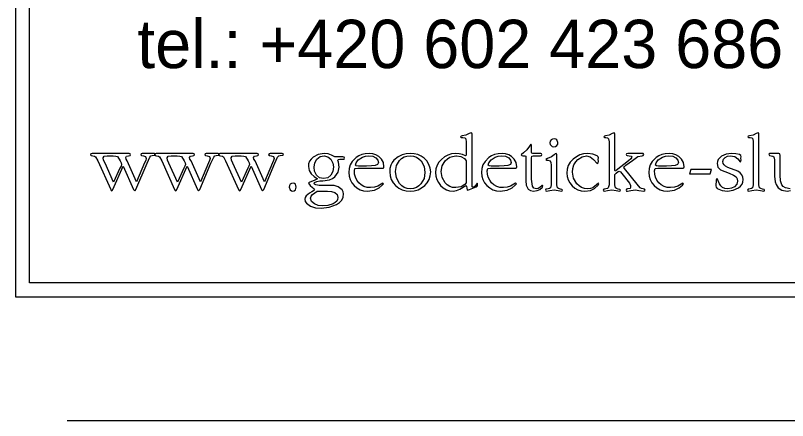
# Model space of a CAD drawing. Extents: x -866693 to -866303, y -1041966 to -1040244.
# Drawn here: x -866432.68 to -866414.49, y -1041642.86 to -1041633.31 of the extents above; entities that cross this region are included whole.
import ezdxf

# ---------------------------------------------------------------- set-up
doc = ezdxf.new("R2010")
doc.units = 0
doc.layers.add('Tabulka', color=7, linetype='Continuous')

msp = doc.modelspace()

# ---------------------------------------------------------------- linework, layer by layer
at = {"layer": 'Tabulka'}
for p, q in [((-866432.683, -1041626.437), (-866432.683, -1041639.941)), ((-866432.353, -1041639.611), (-866432.353, -1041626.768)), ((-866406.437, -1041639.611), (-866432.353, -1041639.611)), ((-866432.683, -1041639.941), (-866404.89, -1041639.941)), ((-866431.466, -1041642.862), (-866338.717, -1041642.862))]:
    msp.add_line(p, q, dxfattribs=at)
for points in [[(-866421.798, -1041637.288), (-866421.798, -1041637.269), (-866421.808, -1041637.262), (-866421.854, -1041637.336), (-866421.897, -1041637.37), (-866421.922, -1041637.351), (-866421.926, -1041637.299), (-866421.926, -1041637.269), (-866421.926, -1041636.107), (-866421.931, -1041636.084), (-866421.945, -1041636.075), (-866421.991, -1041636.097), (-866422.07, -1041636.131), (-866422.156, -1041636.15), (-866422.185, -1041636.159), (-866422.195, -1041636.173), (-866422.175, -1041636.191), (-866422.142, -1041636.191), (-866422.1, -1041636.198), (-866422.076, -1041636.216), (-866422.061, -1041636.294), (-866422.061, -1041636.325), (-866422.061, -1041636.354), (-866422.061, -1041636.545), (-866422.061, -1041636.573), (-866422.065, -1041636.606), (-866422.078, -1041636.618), (-866422.151, -1041636.592), (-866422.226, -1041636.572), (-866422.32, -1041636.565), (-866422.41, -1041636.574), (-866422.497, -1041636.602), (-866422.578, -1041636.646), (-866422.649, -1041636.703), (-866422.708, -1041636.769), (-866422.75, -1041636.843), (-866422.776, -1041636.924), (-866422.785, -1041637.01), (-866422.778, -1041637.097), (-866422.756, -1041637.177), (-866422.719, -1041637.251), (-866422.666, -1041637.32), (-866422.603, -1041637.377), (-866422.532, -1041637.418), (-866422.454, -1041637.442), (-866422.368, -1041637.45), (-866422.294, -1041637.44), (-866422.216, -1041637.409), (-866422.07, -1041637.316), (-866422.054, -1041637.337), (-866422.051, -1041637.379), (-866422.045, -1041637.419), (-866422.03, -1041637.433), (-866421.989, -1041637.414), (-866421.833, -1041637.35), (-866421.805, -1041637.337), (-866421.8, -1041637.314)], [(-866417.851, -1041637.43), (-866417.862, -1041637.405), (-866417.892, -1041637.397), (-866417.934, -1041637.392), (-866417.962, -1041637.376), (-866418.033, -1041637.287), (-866418.337, -1041636.915), (-866418.351, -1041636.891), (-866418.337, -1041636.868), (-866418.301, -1041636.839), (-866418.15, -1041636.726), (-866418.021, -1041636.636), (-866417.921, -1041636.619), (-866417.895, -1041636.615), (-866417.882, -1041636.587), (-866417.893, -1041636.566), (-866417.914, -1041636.565), (-866418.254, -1041636.565), (-866418.287, -1041636.57), (-866418.298, -1041636.586), (-866418.291, -1041636.606), (-866418.272, -1041636.615), (-866418.224, -1041636.619), (-866418.18, -1041636.625), (-866418.162, -1041636.65), (-866418.187, -1041636.692), (-866418.243, -1041636.741), (-866418.532, -1041636.968), (-866418.542, -1041636.976), (-866418.554, -1041636.982), (-866418.565, -1041636.967), (-866418.565, -1041636.941), (-866418.565, -1041636.106), (-866418.569, -1041636.084), (-866418.582, -1041636.075), (-866418.626, -1041636.097), (-866418.7, -1041636.131), (-866418.781, -1041636.15), (-866418.809, -1041636.159), (-866418.818, -1041636.173), (-866418.8, -1041636.191), (-866418.772, -1041636.191), (-866418.735, -1041636.198), (-866418.713, -1041636.216), (-866418.7, -1041636.291), (-866418.7, -1041636.321), (-866418.7, -1041636.35), (-866418.7, -1041637.242), (-866418.7, -1041637.301), (-866418.716, -1041637.373), (-866418.739, -1041637.393), (-866418.772, -1041637.401), (-866418.823, -1041637.409), (-866418.834, -1041637.431), (-866418.827, -1041637.446), (-866418.807, -1041637.45), (-866418.733, -1041637.437), (-866418.63, -1041637.423), (-866418.531, -1041637.44), (-866418.454, -1041637.45), (-866418.437, -1041637.445), (-866418.431, -1041637.428), (-866418.444, -1041637.413), (-866418.482, -1041637.403), (-866418.524, -1041637.393), (-866418.549, -1041637.372), (-866418.565, -1041637.3), (-866418.565, -1041637.241), (-866418.565, -1041637.128), (-866418.559, -1041637.056), (-866418.528, -1041637.025), (-866418.487, -1041636.992), (-866418.459, -1041636.98), (-866418.432, -1041636.995), (-866418.401, -1041637.034), (-866418.219, -1041637.267), (-866418.197, -1041637.319), (-866418.19, -1041637.356), (-866418.205, -1041637.388), (-866418.264, -1041637.397), (-866418.287, -1041637.406), (-866418.298, -1041637.432), (-866418.285, -1041637.45), (-866418.266, -1041637.45), (-866418.184, -1041637.437), (-866418.079, -1041637.423), (-866417.994, -1041637.437), (-866417.883, -1041637.45), (-866417.859, -1041637.445)], [(-866415.033, -1041637.429), (-866415.046, -1041637.413), (-866415.083, -1041637.403), (-866415.125, -1041637.393), (-866415.151, -1041637.373), (-866415.167, -1041637.302), (-866415.167, -1041637.243), (-866415.167, -1041636.107), (-866415.171, -1041636.084), (-866415.184, -1041636.075), (-866415.23, -1041636.097), (-866415.306, -1041636.131), (-866415.39, -1041636.15), (-866415.419, -1041636.159), (-866415.428, -1041636.173), (-866415.409, -1041636.191), (-866415.378, -1041636.191), (-866415.338, -1041636.198), (-866415.315, -1041636.216), (-866415.301, -1041636.291), (-866415.301, -1041636.321), (-866415.301, -1041636.35), (-866415.301, -1041637.242), (-866415.301, -1041637.301), (-866415.317, -1041637.373), (-866415.34, -1041637.393), (-866415.373, -1041637.401), (-866415.424, -1041637.409), (-866415.435, -1041637.431), (-866415.429, -1041637.446), (-866415.409, -1041637.45), (-866415.335, -1041637.437), (-866415.231, -1041637.423), (-866415.132, -1041637.44), (-866415.055, -1041637.45), (-866415.039, -1041637.445)], [(-866420.259, -1041637.329), (-866420.264, -1041637.322), (-866420.272, -1041637.316), (-866420.332, -1041637.367), (-866420.37, -1041637.39), (-866420.41, -1041637.397), (-866420.471, -1041637.381), (-866420.504, -1041637.332), (-866420.523, -1041637.168), (-866420.523, -1041636.672), (-866420.515, -1041636.629), (-866420.485, -1041636.619), (-866420.453, -1041636.619), (-866420.345, -1041636.619), (-866420.313, -1041636.619), (-866420.292, -1041636.612), (-866420.286, -1041636.589), (-866420.29, -1041636.572), (-866420.303, -1041636.565), (-866420.493, -1041636.565), (-866420.519, -1041636.56), (-866420.523, -1041636.539), (-866420.523, -1041636.372), (-866420.539, -1041636.344), (-866420.569, -1041636.389), (-866420.633, -1041636.478), (-866420.714, -1041636.55), (-866420.76, -1041636.585), (-866420.766, -1041636.6), (-866420.757, -1041636.614), (-866420.729, -1041636.619), (-866420.706, -1041636.619), (-866420.683, -1041636.619), (-866420.66, -1041636.628), (-866420.657, -1041636.654), (-866420.657, -1041637.151), (-866420.657, -1041637.212), (-866420.649, -1041637.313), (-866420.604, -1041637.404), (-866420.553, -1041637.439), (-866420.476, -1041637.45), (-866420.389, -1041637.44), (-866420.329, -1041637.41), (-866420.27, -1041637.356)], [(-866419.902, -1041636.308), (-866419.927, -1041636.245), (-866419.956, -1041636.223), (-866419.993, -1041636.216), (-866420.032, -1041636.223), (-866420.063, -1041636.245), (-866420.083, -1041636.275), (-866420.09, -1041636.313), (-866420.084, -1041636.349), (-866420.066, -1041636.379), (-866420.037, -1041636.398), (-866419.997, -1041636.404), (-866419.957, -1041636.398), (-866419.927, -1041636.376), (-866419.909, -1041636.346)], [(-866429.382, -1041636.589), (-866429.389, -1041636.572), (-866429.409, -1041636.565), (-866429.697, -1041636.565), (-866429.722, -1041636.573), (-866429.731, -1041636.598), (-866429.712, -1041636.615), (-866429.669, -1041636.619), (-866429.618, -1041636.634), (-866429.601, -1041636.68), (-866429.614, -1041636.733), (-866429.641, -1041636.787), (-866429.832, -1041637.233), (-866430.051, -1041636.741), (-866430.078, -1041636.695), (-866430.086, -1041636.662), (-866430.065, -1041636.629), (-866430.017, -1041636.619), (-866429.983, -1041636.613), (-866429.972, -1041636.595), (-866429.98, -1041636.573), (-866430.003, -1041636.565), (-866430.878, -1041636.565), (-866430.903, -1041636.573), (-866430.911, -1041636.595), (-866430.899, -1041636.613), (-866430.863, -1041636.619), (-866430.821, -1041636.626), (-866430.793, -1041636.646), (-866430.744, -1041636.734), (-866430.439, -1041637.412), (-866430.428, -1041637.434), (-866430.412, -1041637.443), (-866430.395, -1041637.433), (-866430.385, -1041637.412), (-866430.144, -1041636.86), (-866429.899, -1041637.412), (-866429.889, -1041637.429), (-866429.874, -1041637.443), (-866429.858, -1041637.433), (-866429.848, -1041637.412), (-866429.583, -1041636.79), (-866429.52, -1041636.65), (-866429.493, -1041636.622), (-866429.462, -1041636.61), (-866429.405, -1041636.602)], [(-866430.181, -1041636.821), (-866430.196, -1041636.861), (-866430.223, -1041636.907), (-866430.369, -1041637.242), (-866430.573, -1041636.789), (-866430.605, -1041636.721), (-866430.617, -1041636.668), (-866430.594, -1041636.631), (-866430.521, -1041636.619), (-866430.379, -1041636.619), (-866430.314, -1041636.624), (-866430.275, -1041636.638), (-866430.213, -1041636.737), (-866430.192, -1041636.782)], [(-866427.876, -1041636.589), (-866427.883, -1041636.572), (-866427.904, -1041636.565), (-866428.191, -1041636.565), (-866428.216, -1041636.573), (-866428.225, -1041636.598), (-866428.206, -1041636.615), (-866428.163, -1041636.619), (-866428.112, -1041636.634), (-866428.095, -1041636.68), (-866428.108, -1041636.733), (-866428.135, -1041636.787), (-866428.325, -1041637.233), (-866428.544, -1041636.741), (-866428.572, -1041636.695), (-866428.58, -1041636.662), (-866428.559, -1041636.629), (-866428.511, -1041636.619), (-866428.477, -1041636.613), (-866428.466, -1041636.595), (-866428.474, -1041636.573), (-866428.497, -1041636.565), (-866429.371, -1041636.565), (-866429.397, -1041636.573), (-866429.405, -1041636.595), (-866429.393, -1041636.613), (-866429.357, -1041636.619), (-866429.315, -1041636.626), (-866429.287, -1041636.646), (-866429.238, -1041636.734), (-866428.933, -1041637.412), (-866428.922, -1041637.434), (-866428.906, -1041637.443), (-866428.889, -1041637.433), (-866428.879, -1041637.412), (-866428.638, -1041636.86), (-866428.393, -1041637.412), (-866428.383, -1041637.429), (-866428.367, -1041637.443), (-866428.352, -1041637.433), (-866428.342, -1041637.412), (-866428.077, -1041636.79), (-866428.013, -1041636.65), (-866427.987, -1041636.622), (-866427.956, -1041636.61), (-866427.9, -1041636.602)], [(-866428.675, -1041636.821), (-866428.689, -1041636.861), (-866428.717, -1041636.907), (-866428.864, -1041637.242), (-866429.066, -1041636.789), (-866429.099, -1041636.721), (-866429.111, -1041636.668), (-866429.088, -1041636.631), (-866429.015, -1041636.619), (-866428.874, -1041636.619), (-866428.808, -1041636.624), (-866428.769, -1041636.638), (-866428.707, -1041636.737), (-866428.687, -1041636.782)], [(-866426.369, -1041636.589), (-866426.376, -1041636.572), (-866426.397, -1041636.565), (-866426.684, -1041636.565), (-866426.709, -1041636.573), (-866426.718, -1041636.598), (-866426.7, -1041636.615), (-866426.656, -1041636.619), (-866426.605, -1041636.634), (-866426.588, -1041636.68), (-866426.601, -1041636.733), (-866426.628, -1041636.787), (-866426.819, -1041637.233), (-866427.038, -1041636.741), (-866427.065, -1041636.695), (-866427.073, -1041636.662), (-866427.052, -1041636.629), (-866427.005, -1041636.619), (-866426.97, -1041636.613), (-866426.959, -1041636.595), (-866426.967, -1041636.573), (-866426.99, -1041636.565), (-866427.865, -1041636.565), (-866427.89, -1041636.573), (-866427.898, -1041636.595), (-866427.886, -1041636.613), (-866427.85, -1041636.619), (-866427.808, -1041636.626), (-866427.78, -1041636.646), (-866427.731, -1041636.734), (-866427.426, -1041637.412), (-866427.415, -1041637.434), (-866427.399, -1041637.443), (-866427.382, -1041637.433), (-866427.372, -1041637.412), (-866427.131, -1041636.86), (-866426.886, -1041637.412), (-866426.876, -1041637.429), (-866426.861, -1041637.443), (-866426.845, -1041637.433), (-866426.835, -1041637.412), (-866426.57, -1041636.79), (-866426.507, -1041636.65), (-866426.481, -1041636.622), (-866426.449, -1041636.61), (-866426.393, -1041636.602)], [(-866427.168, -1041636.821), (-866427.183, -1041636.861), (-866427.21, -1041636.907), (-866427.357, -1041637.242), (-866427.56, -1041636.789), (-866427.592, -1041636.721), (-866427.604, -1041636.668), (-866427.581, -1041636.631), (-866427.508, -1041636.619), (-866427.367, -1041636.619), (-866427.301, -1041636.624), (-866427.262, -1041636.638), (-866427.2, -1041636.737), (-866427.18, -1041636.782)], [(-866424.934, -1041636.674), (-866424.94, -1041636.654), (-866424.97, -1041636.646), (-866425.002, -1041636.646), (-866425.099, -1041636.646), (-866425.162, -1041636.642), (-866425.241, -1041636.602), (-866425.317, -1041636.574), (-866425.412, -1041636.565), (-866425.549, -1041636.587), (-866425.67, -1041636.65), (-866425.72, -1041636.696), (-866425.754, -1041636.749), (-866425.776, -1041636.808), (-866425.783, -1041636.873), (-866425.767, -1041636.964), (-866425.718, -1041637.041), (-866425.648, -1041637.105), (-866425.567, -1041637.159), (-866425.63, -1041637.196), (-866425.763, -1041637.246), (-866425.783, -1041637.265), (-866425.742, -1041637.317), (-866425.687, -1041637.367), (-866425.654, -1041637.396), (-866425.637, -1041637.423), (-866425.658, -1041637.447), (-866425.703, -1041637.472), (-866425.756, -1041637.502), (-866425.836, -1041637.563), (-866425.856, -1041637.599), (-866425.863, -1041637.643), (-866425.854, -1041637.694), (-866425.824, -1041637.738), (-866425.729, -1041637.805), (-866425.613, -1041637.842), (-866425.477, -1041637.852), (-866425.295, -1041637.832), (-866425.121, -1041637.768), (-866425.047, -1041637.721), (-866424.993, -1041637.663), (-866424.962, -1041637.595), (-866424.951, -1041637.517), (-866424.96, -1041637.465), (-866424.989, -1041637.42), (-866425.083, -1041637.35), (-866425.178, -1041637.32), (-866425.316, -1041637.316), (-866425.529, -1041637.316), (-866425.608, -1041637.305), (-866425.638, -1041637.29), (-866425.648, -1041637.269), (-866425.635, -1041637.248), (-866425.579, -1041637.228), (-866425.515, -1041637.212), (-866425.438, -1041637.209), (-866425.285, -1041637.185), (-866425.216, -1041637.154), (-866425.159, -1041637.111), (-866425.083, -1041637.005), (-866425.058, -1041636.885), (-866425.074, -1041636.767), (-866425.088, -1041636.718), (-866425.078, -1041636.704), (-866425.044, -1041636.7), (-866425.009, -1041636.7), (-866424.975, -1041636.7), (-866424.94, -1041636.696)], [(-866425.192, -1041636.882), (-866425.208, -1041636.989), (-866425.252, -1041637.077), (-866425.326, -1041637.136), (-866425.428, -1041637.156), (-866425.522, -1041637.135), (-866425.592, -1041637.073), (-866425.634, -1041636.985), (-866425.648, -1041636.884), (-866425.632, -1041636.785), (-866425.584, -1041636.698), (-866425.508, -1041636.639), (-866425.411, -1041636.619), (-866425.323, -1041636.64), (-866425.253, -1041636.702), (-866425.208, -1041636.789)], [(-866424.001, -1041636.881), (-866424.016, -1041636.78), (-866424.061, -1041636.696), (-866424.123, -1041636.633), (-866424.191, -1041636.593), (-866424.265, -1041636.572), (-866424.346, -1041636.565), (-866424.441, -1041636.572), (-866424.524, -1041636.589), (-866424.597, -1041636.62), (-866424.658, -1041636.661), (-866424.749, -1041636.753), (-866424.801, -1041636.834), (-866424.824, -1041636.917), (-866424.832, -1041637.012), (-866424.825, -1041637.1), (-866424.801, -1041637.18), (-866424.761, -1041637.255), (-866424.706, -1041637.322), (-866424.639, -1041637.378), (-866424.564, -1041637.419), (-866424.482, -1041637.442), (-866424.392, -1041637.45), (-866424.227, -1041637.428), (-866424.112, -1041637.373), (-866424.04, -1041637.314), (-866424.011, -1041637.277), (-866424.027, -1041637.262), (-866424.149, -1041637.337), (-866424.228, -1041637.362), (-866424.317, -1041637.37), (-866424.399, -1041637.363), (-866424.473, -1041637.341), (-866424.538, -1041637.305), (-866424.594, -1041637.254), (-866424.639, -1041637.193), (-866424.672, -1041637.126), (-866424.692, -1041637.052), (-866424.698, -1041636.973), (-866424.684, -1041636.921), (-866424.618, -1041636.914), (-866424.024, -1041636.914), (-866424.006, -1041636.906)], [(-866424.134, -1041636.776), (-866424.153, -1041636.823), (-866424.212, -1041636.847), (-866424.296, -1041636.858), (-866424.415, -1041636.86), (-866424.441, -1041636.86), (-866424.603, -1041636.86), (-866424.654, -1041636.858), (-866424.672, -1041636.838), (-866424.655, -1041636.785), (-866424.607, -1041636.716), (-866424.509, -1041636.649), (-866424.439, -1041636.626), (-866424.362, -1041636.619), (-866424.264, -1041636.631), (-866424.191, -1041636.669), (-866424.149, -1041636.723)], [(-866422.9, -1041637), (-866422.911, -1041636.91), (-866422.942, -1041636.821), (-866422.99, -1041636.741), (-866423.053, -1041636.675), (-866423.126, -1041636.625), (-866423.205, -1041636.591), (-866423.29, -1041636.572), (-866423.383, -1041636.565), (-866423.482, -1041636.573), (-866423.575, -1041636.596), (-866423.668, -1041636.644), (-866423.766, -1041636.723), (-866423.81, -1041636.776), (-866423.841, -1041636.84), (-866423.86, -1041636.915), (-866423.866, -1041637), (-866423.858, -1041637.094), (-866423.831, -1041637.179), (-866423.788, -1041637.255), (-866423.726, -1041637.323), (-866423.652, -1041637.379), (-866423.57, -1041637.419), (-866423.481, -1041637.442), (-866423.383, -1041637.45), (-866423.287, -1041637.442), (-866423.198, -1041637.419), (-866423.116, -1041637.378), (-866423.042, -1041637.322), (-866422.98, -1041637.254), (-866422.936, -1041637.177), (-866422.91, -1041637.093)], [(-866423.035, -1041637.013), (-866423.058, -1041637.151), (-866423.129, -1041637.277), (-866423.179, -1041637.33), (-866423.238, -1041637.367), (-866423.304, -1041637.39), (-866423.376, -1041637.397), (-866423.454, -1041637.389), (-866423.522, -1041637.365), (-866423.583, -1041637.326), (-866423.635, -1041637.269), (-866423.708, -1041637.137), (-866423.732, -1041636.992), (-866423.709, -1041636.851), (-866423.638, -1041636.73), (-866423.588, -1041636.682), (-866423.528, -1041636.647), (-866423.461, -1041636.626), (-866423.384, -1041636.619), (-866423.307, -1041636.626), (-866423.238, -1041636.649), (-866423.178, -1041636.687), (-866423.127, -1041636.74), (-866423.058, -1041636.868)], [(-866422.061, -1041637.189), (-866422.061, -1041637.22), (-866422.065, -1041637.254), (-866422.094, -1041637.298), (-866422.183, -1041637.349), (-866422.312, -1041637.37), (-866422.385, -1041637.363), (-866422.451, -1041637.341), (-866422.509, -1041637.305), (-866422.559, -1041637.255), (-866422.628, -1041637.133), (-866422.651, -1041636.992), (-866422.628, -1041636.855), (-866422.558, -1041636.739), (-866422.507, -1041636.691), (-866422.449, -1041636.655), (-866422.384, -1041636.632), (-866422.31, -1041636.619), (-866422.29, -1041636.619), (-866422.189, -1041636.635), (-866422.107, -1041636.679), (-866422.068, -1041636.741), (-866422.061, -1041636.829), (-866422.061, -1041636.852)], [(-866420.872, -1041636.881), (-866420.887, -1041636.78), (-866420.932, -1041636.696), (-866420.995, -1041636.633), (-866421.062, -1041636.593), (-866421.136, -1041636.572), (-866421.217, -1041636.565), (-866421.313, -1041636.572), (-866421.396, -1041636.589), (-866421.469, -1041636.62), (-866421.529, -1041636.661), (-866421.62, -1041636.753), (-866421.672, -1041636.834), (-866421.696, -1041636.917), (-866421.704, -1041637.012), (-866421.696, -1041637.1), (-866421.672, -1041637.18), (-866421.633, -1041637.255), (-866421.577, -1041637.322), (-866421.51, -1041637.378), (-866421.435, -1041637.419), (-866421.353, -1041637.442), (-866421.263, -1041637.45), (-866421.099, -1041637.428), (-866420.984, -1041637.373), (-866420.912, -1041637.314), (-866420.883, -1041637.277), (-866420.899, -1041637.262), (-866421.02, -1041637.337), (-866421.1, -1041637.362), (-866421.189, -1041637.37), (-866421.271, -1041637.363), (-866421.344, -1041637.341), (-866421.41, -1041637.305), (-866421.466, -1041637.254), (-866421.511, -1041637.193), (-866421.543, -1041637.126), (-866421.563, -1041637.052), (-866421.569, -1041636.973), (-866421.556, -1041636.921), (-866421.489, -1041636.914), (-866420.896, -1041636.914), (-866420.878, -1041636.906)], [(-866421.006, -1041636.776), (-866421.024, -1041636.823), (-866421.083, -1041636.847), (-866421.168, -1041636.858), (-866421.287, -1041636.86), (-866421.313, -1041636.86), (-866421.475, -1041636.86), (-866421.525, -1041636.858), (-866421.543, -1041636.838), (-866421.527, -1041636.785), (-866421.479, -1041636.716), (-866421.38, -1041636.649), (-866421.31, -1041636.626), (-866421.233, -1041636.619), (-866421.136, -1041636.631), (-866421.063, -1041636.669), (-866421.02, -1041636.723)], [(-866419.795, -1041637.429), (-866419.808, -1041637.413), (-866419.846, -1041637.404), (-866419.888, -1041637.393), (-866419.913, -1041637.373), (-866419.929, -1041637.303), (-866419.929, -1041637.245), (-866419.929, -1041636.596), (-866419.933, -1041636.573), (-866419.946, -1041636.565), (-866419.967, -1041636.573), (-866419.991, -1041636.597), (-866420.055, -1041636.642), (-866420.146, -1041636.682), (-866420.187, -1041636.71), (-866420.164, -1041636.724), (-866420.139, -1041636.724), (-866420.084, -1041636.737), (-866420.069, -1041636.779), (-866420.063, -1041636.839), (-866420.063, -1041636.867), (-866420.063, -1041637.24), (-866420.063, -1041637.3), (-866420.08, -1041637.372), (-866420.102, -1041637.392), (-866420.136, -1041637.401), (-866420.187, -1041637.409), (-866420.198, -1041637.431), (-866420.191, -1041637.446), (-866420.171, -1041637.45), (-866420.097, -1041637.437), (-866419.993, -1041637.423), (-866419.895, -1041637.44), (-866419.818, -1041637.45), (-866419.801, -1041637.445)], [(-866418.938, -1041637.279), (-866418.951, -1041637.262), (-866418.991, -1041637.304), (-866419.08, -1041637.372), (-866419.138, -1041637.39), (-866419.201, -1041637.397), (-866419.276, -1041637.39), (-866419.344, -1041637.367), (-866419.405, -1041637.33), (-866419.459, -1041637.277), (-866419.536, -1041637.149), (-866419.561, -1041637.005), (-866419.552, -1041636.919), (-866419.525, -1041636.835), (-866419.484, -1041636.762), (-866419.435, -1041636.707), (-866419.33, -1041636.641), (-866419.228, -1041636.619), (-866419.143, -1041636.642), (-866419.067, -1041636.708), (-866418.976, -1041636.798), (-866418.956, -1041636.785), (-866418.951, -1041636.743), (-866418.953, -1041636.705), (-866418.951, -1041636.67), (-866418.959, -1041636.64), (-866418.981, -1041636.616), (-866419.077, -1041636.58), (-866419.201, -1041636.565), (-866419.297, -1041636.574), (-866419.386, -1041636.599), (-866419.469, -1041636.641), (-866419.546, -1041636.7), (-866419.612, -1041636.771), (-866419.659, -1041636.849), (-866419.686, -1041636.934), (-866419.695, -1041637.025), (-866419.688, -1041637.109), (-866419.664, -1041637.187), (-866419.626, -1041637.259), (-866419.57, -1041637.324), (-866419.505, -1041637.38), (-866419.433, -1041637.419), (-866419.355, -1041637.443), (-866419.27, -1041637.45), (-866419.133, -1041637.436), (-866419.043, -1041637.393), (-866418.957, -1041637.313)], [(-866416.932, -1041636.881), (-866416.947, -1041636.78), (-866416.992, -1041636.696), (-866417.054, -1041636.633), (-866417.122, -1041636.593), (-866417.197, -1041636.572), (-866417.277, -1041636.565), (-866417.373, -1041636.572), (-866417.456, -1041636.589), (-866417.529, -1041636.62), (-866417.59, -1041636.661), (-866417.68, -1041636.753), (-866417.732, -1041636.834), (-866417.756, -1041636.917), (-866417.764, -1041637.012), (-866417.757, -1041637.1), (-866417.732, -1041637.18), (-866417.693, -1041637.255), (-866417.637, -1041637.322), (-866417.571, -1041637.378), (-866417.496, -1041637.419), (-866417.414, -1041637.442), (-866417.324, -1041637.45), (-866417.158, -1041637.428), (-866417.044, -1041637.373), (-866416.972, -1041637.314), (-866416.943, -1041637.277), (-866416.959, -1041637.262), (-866417.08, -1041637.337), (-866417.16, -1041637.362), (-866417.249, -1041637.37), (-866417.331, -1041637.363), (-866417.404, -1041637.341), (-866417.469, -1041637.305), (-866417.526, -1041637.254), (-866417.571, -1041637.193), (-866417.604, -1041637.126), (-866417.623, -1041637.052), (-866417.63, -1041636.973), (-866417.616, -1041636.921), (-866417.549, -1041636.914), (-866416.956, -1041636.914), (-866416.938, -1041636.906)], [(-866417.066, -1041636.776), (-866417.085, -1041636.823), (-866417.144, -1041636.847), (-866417.228, -1041636.858), (-866417.347, -1041636.86), (-866417.373, -1041636.86), (-866417.535, -1041636.86), (-866417.585, -1041636.858), (-866417.604, -1041636.838), (-866417.587, -1041636.785), (-866417.539, -1041636.716), (-866417.44, -1041636.649), (-866417.37, -1041636.626), (-866417.293, -1041636.619), (-866417.196, -1041636.631), (-866417.122, -1041636.669), (-866417.08, -1041636.723)], [(-866415.537, -1041637.179), (-866415.545, -1041637.119), (-866415.568, -1041637.066), (-866415.607, -1041637.021), (-866415.662, -1041636.983), (-866415.9, -1041636.891), (-866415.952, -1041636.865), (-866415.99, -1041636.834), (-866416.012, -1041636.798), (-866416.02, -1041636.756), (-866416.006, -1041636.701), (-866415.964, -1041636.657), (-866415.906, -1041636.628), (-866415.843, -1041636.619), (-866415.739, -1041636.637), (-866415.668, -1041636.692), (-866415.61, -1041636.765), (-866415.593, -1041636.751), (-866415.59, -1041636.718), (-866415.591, -1041636.677), (-866415.59, -1041636.641), (-866415.597, -1041636.61), (-866415.628, -1041636.592), (-866415.709, -1041636.573), (-866415.816, -1041636.565), (-866415.943, -1041636.579), (-866416.05, -1041636.627), (-866416.127, -1041636.704), (-866416.147, -1041636.75), (-866416.154, -1041636.8), (-866416.134, -1041636.886), (-866416.075, -1041636.946), (-866415.87, -1041637.032), (-866415.767, -1041637.072), (-866415.708, -1041637.115), (-866415.68, -1041637.161), (-866415.67, -1041637.214), (-866415.688, -1041637.29), (-866415.741, -1041637.347), (-866415.817, -1041637.384), (-866415.902, -1041637.397), (-866415.971, -1041637.389), (-866416.026, -1041637.367), (-866416.069, -1041637.328), (-866416.097, -1041637.276), (-866416.15, -1041637.156), (-866416.166, -1041637.166), (-866416.174, -1041637.197), (-866416.18, -1041637.324), (-866416.178, -1041637.361), (-866416.153, -1041637.393), (-866416.033, -1041637.435), (-866415.906, -1041637.45), (-866415.774, -1041637.432), (-866415.652, -1041637.377), (-866415.602, -1041637.337), (-866415.565, -1041637.291), (-866415.544, -1041637.238)], [(-866416.283, -1041636.941), (-866416.771, -1041636.941), (-866416.802, -1041637.048), (-866416.314, -1041637.048)], [(-866426.07, -1041637.356), (-866426.087, -1041637.29), (-866426.11, -1041637.269), (-866426.144, -1041637.262), (-866426.18, -1041637.269), (-866426.208, -1041637.288), (-866426.225, -1041637.319), (-866426.231, -1041637.356), (-866426.209, -1041637.423), (-866426.183, -1041637.443), (-866426.147, -1041637.45), (-866426.113, -1041637.444), (-866426.088, -1041637.425)], [(-866425.085, -1041637.599), (-866425.093, -1041637.647), (-866425.114, -1041637.688), (-866425.15, -1041637.723), (-866425.201, -1041637.75), (-866425.32, -1041637.787), (-866425.444, -1041637.799), (-866425.549, -1041637.787), (-866425.641, -1041637.753), (-866425.705, -1041637.695), (-866425.729, -1041637.619), (-866425.719, -1041637.57), (-866425.686, -1041637.528), (-866425.572, -1041637.45), (-866425.331, -1041637.45), (-866425.239, -1041637.459), (-866425.159, -1041637.482), (-866425.104, -1041637.528)]]:
    msp.add_lwpolyline(points, close=True, dxfattribs=at)
msp.add_lwpolyline([(-866414.429, -1041637.397), (-866414.545, -1041637.373), (-866414.594, -1041637.345), (-866414.627, -1041637.307), (-866414.659, -1041637.208), (-866414.665, -1041637.076), (-866414.665, -1041636.638), (-866414.665, -1041636.608), (-866414.673, -1041636.576), (-866414.697, -1041636.565), (-866414.908, -1041636.565), (-866414.933, -1041636.581), (-866414.922, -1041636.61), (-866414.883, -1041636.619), (-866414.84, -1041636.625), (-866414.814, -1041636.642), (-866414.799, -1041636.711), (-866414.799, -1041636.773), (-866414.799, -1041637.067), (-866414.799, -1041637.101), (-866414.787, -1041637.235), (-866414.763, -1041637.298), (-866414.714, -1041637.372), (-866414.63, -1041637.431), (-866414.504, -1041637.45), (-866414.421, -1041637.44)], dxfattribs=at)

# ---------------------------------------------------------------- texts
msp.add_text('tel.: +420 602 423 686', height=1.14013, dxfattribs=at).set_placement((-866429.814, -1041634.551))

doc.saveas('drawing.dxf')
